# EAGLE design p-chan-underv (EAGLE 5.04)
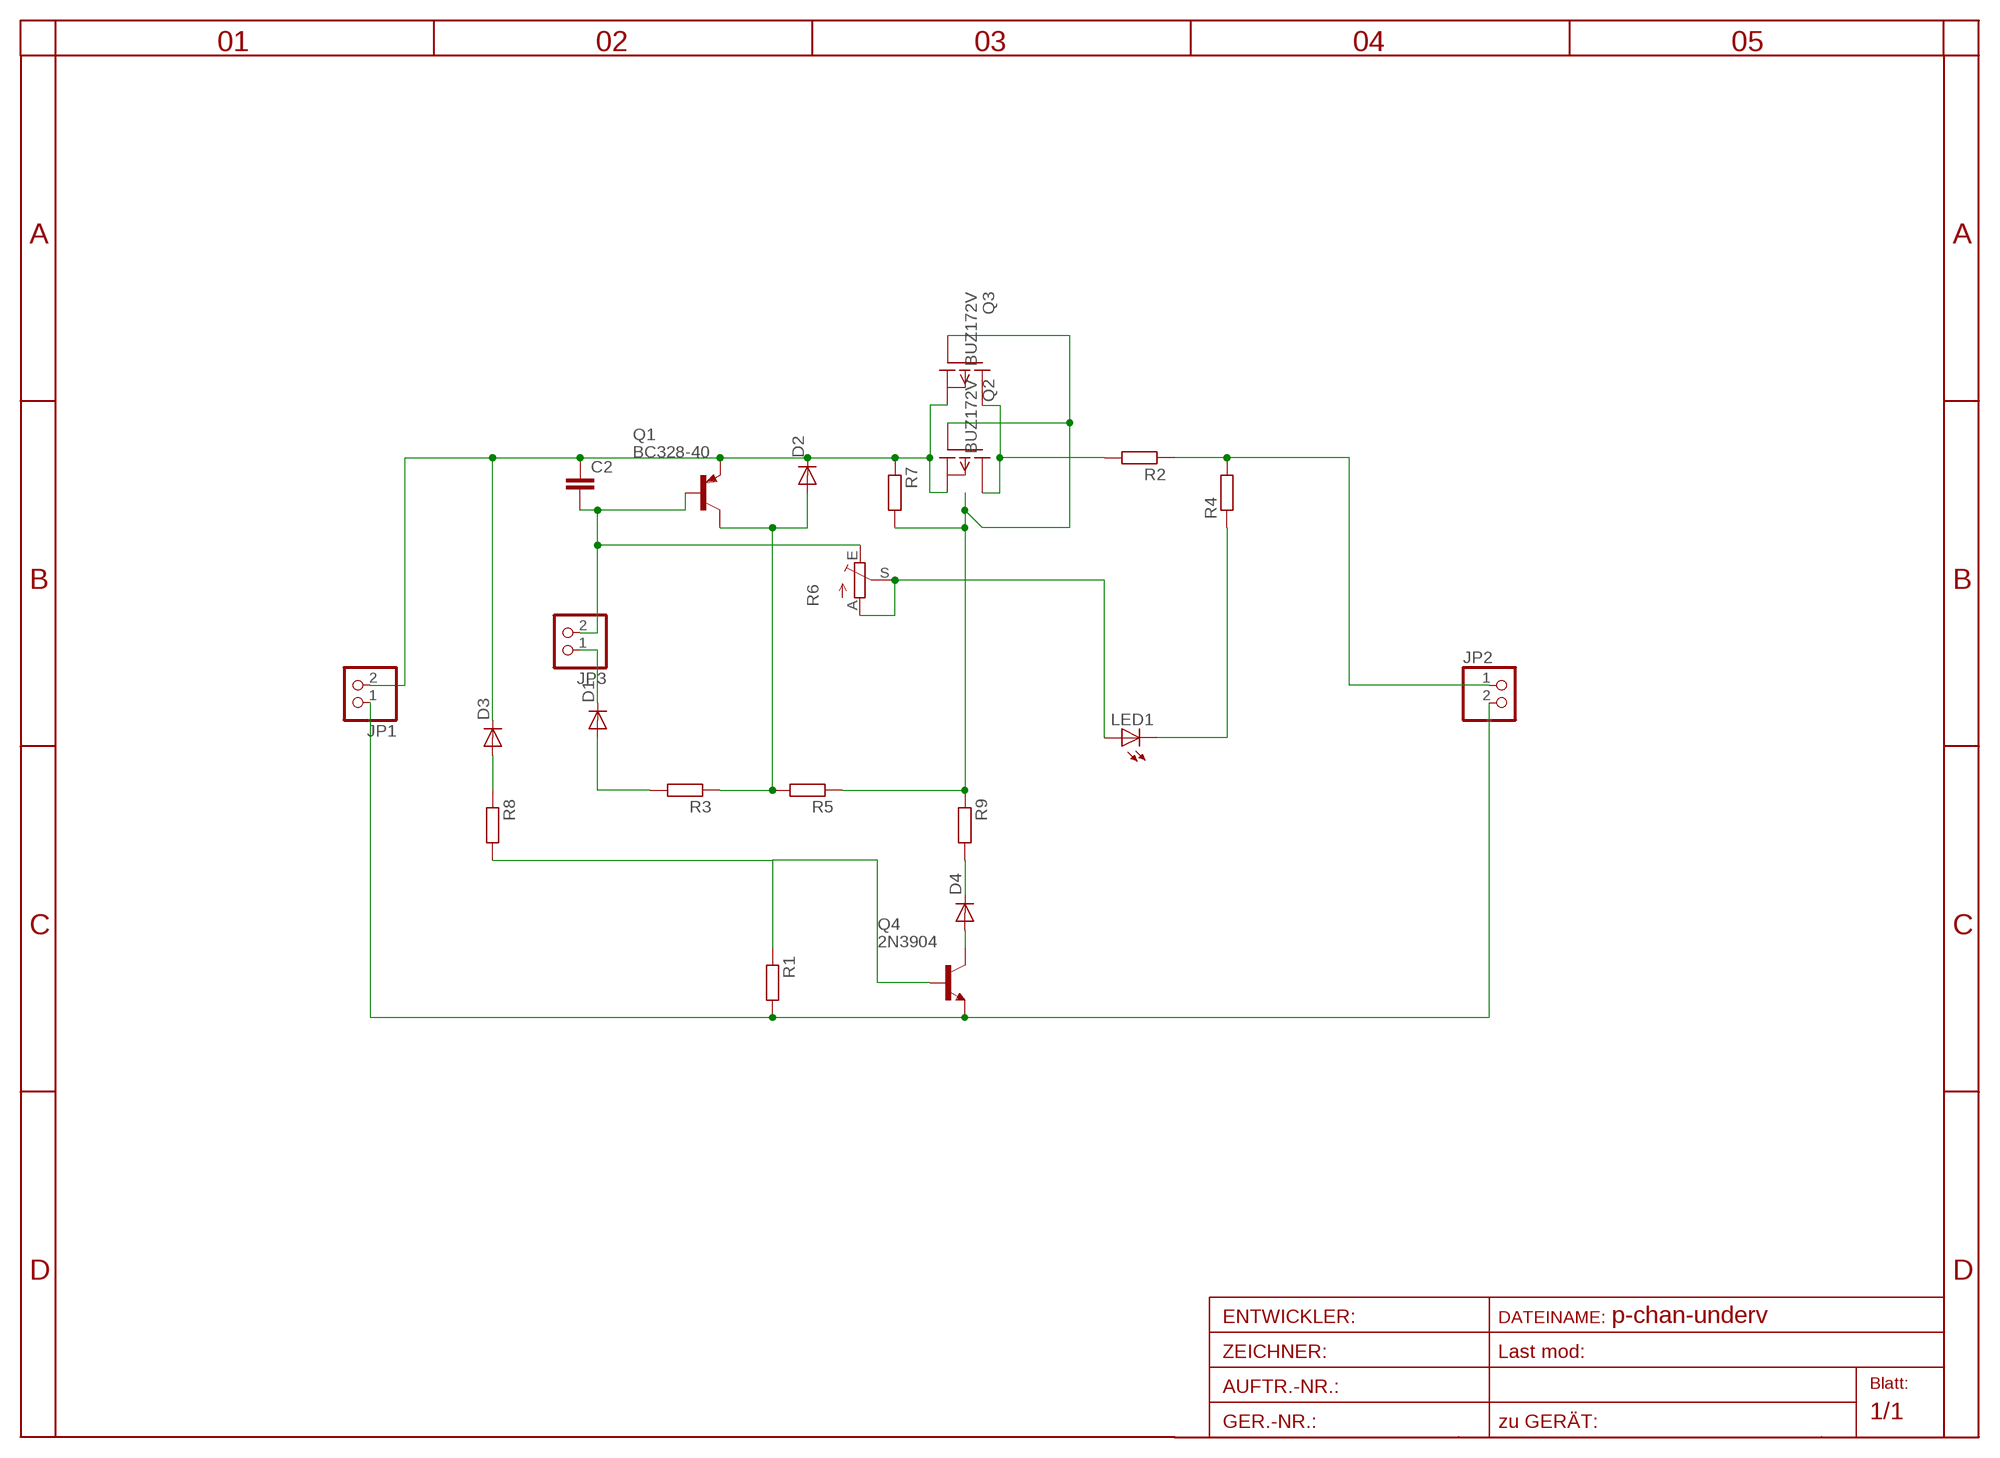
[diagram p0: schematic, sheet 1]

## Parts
C2  C-EU025-024X044  [C025-024X044]
D1  DIODE-D-7.5  [D-7.5]
D2  DIODE-D-5  [D-5]
D3  DIODE-D-10  [D-10]
D4  DIODE-D-2.5  [D-2.5]
JP1  PINHD-1X2  [1X02]
JP2  PINHD-1X2  [1X02]
JP3  PINHD-1X2  [1X02]
LED1  LED3MM  [LED3MM]
Q1  BC328-40  [TO92-EBC]
Q2  BUZ172V  [TO220V]
Q3  BUZ172V  [TO220V]
Q4  2N3904  [TO92]
R1  R-EU_0204/5  [0204/5]
R2  R-EU_0204/5  [0204/5]
R3  R-EU_0204/7  [0204/7]
R4  R-EU_0207/40  [0207/40]
R5  R-EU_0204/5  [0204/5]
R6  TRIM_EU-CA6V  [CA6V]
R7  R-EU_0204/7  [0204/7]
R8  R-EU_0204/5  [0204/5]
R9  R-EU_0204/7  [0204/7]

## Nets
N$3: LED1.A R6.A R6.S
N$4: D2.A Q1.C R3.1 R5.2
N$5: D1.A R3.2
N$6: D1.C JP3.1
N$7: Q2.1(G) Q3.1(G) R5.1 R7.2 R9.1
N$9: Q2.2(D) Q3.2(D) R2.2
N$10: D3.A R8.1
N$11: LED1.K(C) R4.1
N$12: C2.2 JP3.2 Q1.B R6.E
N$13: Q4.2(B) R1.1 R8.2
N$14: D4.A Q4.1(C)
N$15: D4.C R9.2
V+IN: C2.1 D2.C D3.C JP1.2 Q1.E Q2.3(S) Q3.3(S) R7.1
V+OUT: JP2.1 R2.1 R4.2
V-: JP1.1 JP2.2 Q4.3(E) R1.2

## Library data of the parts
C2 = rcl-2:C-EU: CAPACITOR, European symbol
D1-D4 = diode-1:DIODE-: DIODE
JP1-JP3 = pinhead:PINHD-1X2: PIN HEADER
LED1 = led:LED: LED
Q1 = transistor-pnp:BC328*: PNP Transistror
Q2 Q3 = transistor-fet:BUZ172: P-Channel Enhancement MOSFET -100V; -5A; 0,8Ohm
Q4 = transistor-npn:2N3904: NPN Transistor
R1-R5 R7-R9 = rcl-2:R-EU_: RESISTOR, European symbol
R6 = pot:TRIM_EU-: POTENTIOMETER

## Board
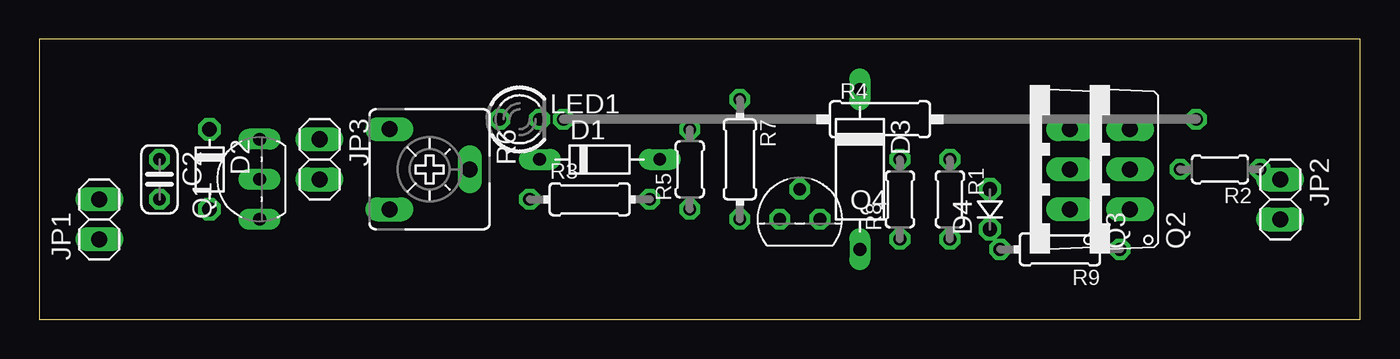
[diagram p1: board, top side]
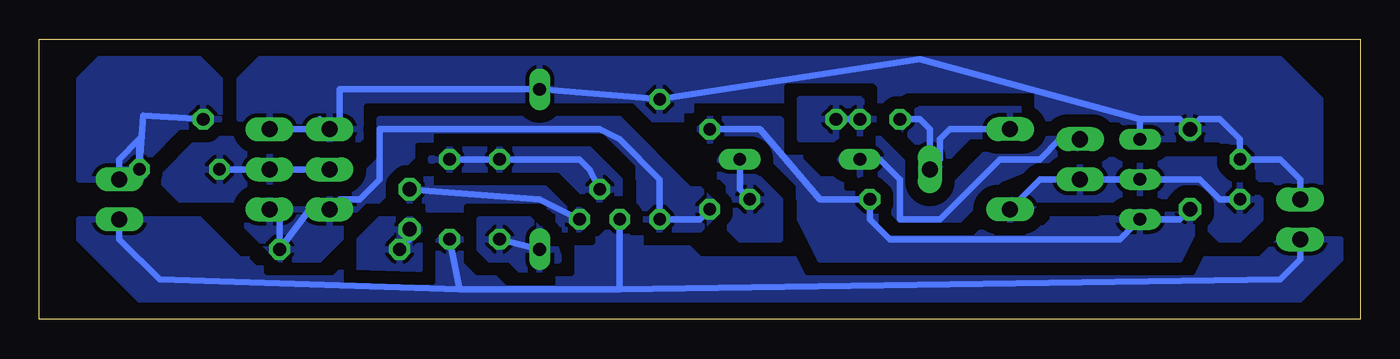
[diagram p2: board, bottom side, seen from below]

Size 83.82 x 17.78 mm. Coordinates in mm from the lower left corner, seen from the top.
Outline: 0,0 83.82,0 83.82,17.78 0,17.78 0,0
Copper layers (1*16): Top 0.035mm / dielectric 1.5mm / Bottom 0.035mm
Design rules "default": minimum track width 10mil, minimum drill 24mil, track to track 8mil, track to pad 8mil, pad to pad 8mil, via to via 8mil, smd to smd 8mil, copper to edge 40mil, drill to drill 8mil, minimum pad ring 10mil, minimum via ring 8mil, stop-mask expansion 4mil, vias tented up to drill 0mil, thermal gap 10mil

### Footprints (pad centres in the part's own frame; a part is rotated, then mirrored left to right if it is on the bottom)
C025-024X044 = drill 0.813 octagon: 1 -1.27,0; 2 1.27,0
D-7.5 = drill 0.813 long: A 3.81,0; C -3.81,0
D-5 = drill 0.9 octagon: A 2.54,0; C -2.54,0
D-10 = drill 0.813 long: A 5.08,0; C -5.08,0
D-2.5 = drill 0.9 octagon: A 1.27,0; C -1.27,0
1X02 = drill 1.016 long: 1 -1.27,0; 2 1.27,0
LED3MM = drill 0.813 octagon: A -1.27,0; K 1.27,0
TO92-EBC = drill 0.813 long: B 0,-1.27; C -2.54,-1.27; E 2.54,-1.27
TO220V = drill 1.016 long: 1 -2.54,-2.54; 2 0,-2.54; 3 2.54,-2.54
TO92 = drill 0.813 octagon: 1 1.27,0; 2 0,1.905; 3 -1.27,0
0204/5 = drill 0.813 octagon: 1 -2.54,0; 2 2.54,0
0204/7 = drill 0.813 octagon: 1 -3.81,0; 2 3.81,0
0207/40 = drill 0.813 octagon: 1 -20.08,0; 2 20.08,0
CA6V = drill 1.016 long: A -2.54,-2.54; E 2.54,-2.54; S 0,2.54

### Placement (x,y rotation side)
C2  7.62,8.89 270 top
D1  35.56,10.16 0 top
D2  10.79,9.53 270 top
D3  52.07,9.53 270 top
D4  60.33,6.99 90 top
JP1  3.81,6.35 90 top
JP2  78.74,7.62 270 top
JP3  17.78,10.16 270 top
LED1  30.48,12.7 0 top
Q1  12.7,8.89 90 top
Q2  66.67,9.53 90 top
Q3  62.87,9.53 90 top
Q4  48.26,6.35 0 top
R1  57.78,7.62 270 top
R2  74.93,9.53 180 top
R3  34.92,7.62 0 top
R4  53.34,12.7 0 top
R5  41.27,9.53 90 top
R6  24.77,9.53 270 top
R7  44.45,10.16 270 top
R8  54.61,7.62 90 top
R9  64.77,4.45 180 top

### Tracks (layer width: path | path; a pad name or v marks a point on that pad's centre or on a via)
N$3
  Bottom 0.406: R6.A 26.04,12.06 26.67,11.43 26.67,10.16 R6.S 27.3,12.06 27.94,12.7 LED1.A
  pour Bottom (isolate 0.813, rank 3): 21.59,13.34 27.94,13.34 29.21,12.7 29.21,10.16 27.94,8.89 25.4,8.89 24.13,10.16
N$4
  Bottom 0.406: D2.A 11.43,6.35 Q1.C 15.24,5.08 29.84,5.08 31.11,6.35 R3.1 34.29,7.62 38.1,12.06 R5.2
  pour Bottom (isolate 0.813, rank 4): 10.16,7.62 10.16,6.35 11.43,3.81 34.29,3.81 35.56,6.35 35.56,7.62 38.1,10.16 40.64,10.16 41.91,11.43 41.91,12.7 36.83,12.7 35.56,11.43 35.56,10.16 34.29,8.89 31.75,8.89 29.21,6.35 16.51,6.35 15.24,7.62
N$5
  Bottom 0.406: D1.A 39.37,8.26 R3.2
  pour Bottom (isolate 0.813, rank 3): 40.64,10.16 40.64,6.35 39.37,5.08 36.83,5.08 36.83,7.62 38.1,8.89
N$6
  Bottom 0.406: JP3.1 19.05,11.43 20.32,10.16 22.86,10.16 26.67,6.35 29.21,6.35 29.21,8.89 30.48,10.16 D1.C
  pour Bottom (isolate 0.813, rank 2): 16.51,11.43 22.86,11.43 26.67,7.62 30.48,11.43 31.75,11.43 33.02,10.16 29.21,6.35 25.4,6.35 22.86,8.89
N$7
  Bottom 0.406: R5.1 41.91,6.35 R7.2 44.45,8.89 46.99,11.43 48.26,12.06 62.23,12.06 62.23,8.89 63.5,7.62 64.77,7.62 Q3.1 66.67,6.99 R9.1 68.58,6.35 Q2.1
  pour Bottom (isolate 0.813, rank 2): 68.58,7.62 71.12,7.62 71.12,6.35 68.58,3.81 66.04,3.81 62.23,7.62 60.96,8.89 60.96,9.53 59.69,10.79 47.62,10.79 45.72,8.89 45.72,6.35 45.09,5.71 41.91,5.71 41.27,6.35 41.27,7.62 41.91,8.26 42.55,8.26 46.99,12.7 62.23,12.7 62.23,10.16 64.77,7.62
N$9
  Bottom 0.406: Q3.2 Q2.2 R2.2
  pour Bottom (isolate 0.813): 71.12,11.43 73.66,11.43 76.2,8.89 74.93,7.62 67.31,7.62 66.04,8.89 66.04,10.16
N$10
  Bottom 0.406: D3.A R8.1
  pour Bottom (isolate 0.813): 51.44,5.71 52.07,5.71 52.7,6.35 55.88,6.35 55.88,4.45 55.24,3.81 53.98,3.81 53.34,3.17 51.44,3.17 50.8,3.81
N$11
  Bottom 0.406: LED1.K R4.1
  pour Bottom (isolate 0.813): 30.48,12.7 31.75,13.97 35.56,13.97 35.56,11.43 30.48,11.43
N$12
  Bottom 0.406: C2.2 8.89,7.62 10.16,8.89 Q1.B JP3.2 20.32,8.89 R6.E
  pour Bottom (isolate 0.813, rank 3): 6.35,7.62 6.35,6.35 7.62,5.08 8.89,5.08 11.43,7.62 20.32,7.62 21.59,6.35 24.13,6.35 24.13,7.62 21.59,7.62 19.05,10.16 8.89,10.16
N$13
  Bottom 0.406: Q4.2 48.9,9.53 49.53,10.16 R8.2 R1.1
  pour Bottom (isolate 0.813): 46.99,7.62 46.99,8.89 48.9,10.79 58.42,10.79 59.05,10.16 58.42,9.53 50.8,9.53 48.9,7.62
N$14
  Bottom 0.406: Q4.1 52.07,7.62 D4.A
  pour Bottom (isolate 0.813, rank 3): 49.53,6.35 49.53,5.71 51.44,5.71 52.7,6.99 60.96,6.99 60.96,8.89 51.44,8.89 49.53,6.99
N$15
  Bottom 0.406: D4.C 60.33,5.08 R9.2
  pour Bottom (isolate 0.813): 59.69,6.35 62.23,6.35 63.5,5.08 63.5,3.17 59.69,3.17
V+IN
  Bottom 0.406: JP1.2 3.81,8.89 5.08,10.16 C2.1 7.62,11.43 8.89,12.7 10.16,12.7 D2.C 11.43,12.7 13.97,12.7 | 13.97,12.7 Q1.E | 13.97,12.7 27.94,16.51 R7.1 D3.C 64.77,14.61 64.77,12.06 | 66.04,12.7 Q3.3 64.77,12.06 | 64.77,12.06 Q2.3
  pour Bottom (isolate 0.813, rank 5): 2.54,7.62 2.54,13.97 3.81,15.24 5.08,16.51 69.85,16.51 71.12,15.24 71.12,12.7 69.85,11.43 63.5,11.43 62.23,12.7 15.24,12.7 13.97,11.43 8.89,11.43 5.08,7.62
V+OUT
  Bottom 0.406: R4.2 77.23,12.94 R2.1 77.47,11.43 78.74,10.16 JP2.1
  pour Bottom (isolate 0.813, rank 5): 72.39,12.7 72.39,15.24 73.66,16.51 80.01,16.51 81.28,15.24 81.28,8.89 77.47,8.89
V-
  Bottom 0.406: JP1.1 3.81,3.81 5.08,2.54 46.99,1.91 | 46.99,1.91 57.15,1.91 | 57.15,1.91 76.2,2.54 78.74,5.08 JP2.2 | 46.99,1.91 Q4.3 | 57.15,1.91 R1.2
  pour Bottom (isolate 0.813, rank 5): 1.27,5.08 1.27,3.81 2.54,2.54 3.81,1.27 77.47,1.27 81.28,5.08 81.28,6.35 76.2,6.35 73.66,6.35 71.12,3.81 59.69,3.81 58.42,5.08 48.26,5.08 46.99,6.35 44.45,6.35 41.91,3.81 6.35,3.81 5.08,5.08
